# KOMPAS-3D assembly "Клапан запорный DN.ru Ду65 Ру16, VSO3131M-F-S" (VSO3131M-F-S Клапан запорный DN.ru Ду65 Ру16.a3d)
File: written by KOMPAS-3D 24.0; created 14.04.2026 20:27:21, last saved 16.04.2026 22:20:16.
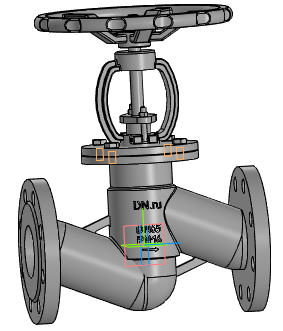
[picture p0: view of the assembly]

Document properties: Автор: R2D2; Полное имя файла: E:\Работа\Зайцев\VSO3131M-F-S Клапан запорный DN.ru Ду15-100 Ру16\DN65\исходные материалы\VSO3131M-F-S Клапан запорный DN.ru Ду65 Ру16.a3d

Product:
- Component [detail]: Корпус  | qty 1  | pos. 1  | Масса: 6.9; Автор: R2D2; source file: Корпус.m3d
- Component [detail]: Клапан запорный DN.ru Ду65 Ру16  | designation VSO1121M-F-S  | qty 1  | pos. 2  | Масса: 19.42; Раздел спецификации: Прочие изделия; Примечание: D090-01948; Автор: R2D2; source file: 2.m3d
- Component [standard]: Hexagon head screw ISO 4017 - М10 x 20  | qty 4  | Масса: 0.023019; Раздел спецификации: Стандартные изделия; Рассекать на разрезах: no
- Part/product: Клапан запорный DN.ru Ду65 Ру16  | designation VSO3131M-F-S
    Масса: 16
    Раздел спецификации: Прочие изделия
    Примечание: D090-02952

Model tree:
1. Массив по концентрической сетке:1  (with: Грань.Элемент вращения:2, Грань.Операция без истории:1)  (labels: Грань.Элемент выдавливания:9.Экземпляр ( 1, 2 ))  (4 pattern instances)
     Шаг 2 = 360; Расстояние = -290

Expressions: D090-01948
Referenced files in E:\Работа\Зайцев\VSO3131M-F-S Клапан запорный DN.ru Ду15-100 Ру40\DN65\исходные материалы\: Корпус.m3d, 2.m3d
Referenced files in E:\Работа\Зайцев\VSO3131M-F-S Клапан запорный DN.ru Ду15-100 Ру16\DN65\исходные материалы\: Корпус.m3d, 2.m3d
Referenced files in C:\Program Files\ASCON\KOMPAS-3D v24\Libs\PolynomLib\DATA\vault\Methods\Kompas\3D\: PLib_Bolt_1_ISO_1100.m3d
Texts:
  VSO1121M-F-S
  Hexagon head screw
  BOSimple***PART:c031cb5e-65ec-2f83-1ced-75228c8ad34f***PART:A259_7B16EF33AB1642D2[16;1,5;20;10;-;Undefined]
  Программные изделия  и базы данных
  VSO3131M-F-S
  VSO1121M-F-S Клапан запорный DN.ru Ду65 Ру16
  Hexagon head screw ISO 4017 - М10 x 20 (1)
  hole1
  hole2
  Hexagon head screw ISO 4017 - М10 x 20 (2)
  Hexagon head screw ISO 4017 - М10 x 20 (3)
  Hexagon head screw ISO 4017 - М10 x 20 (4)
  Ось Y.Начало координат
  Плоскость XY.Начало координат
  Плоскость ZX.Начало координат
